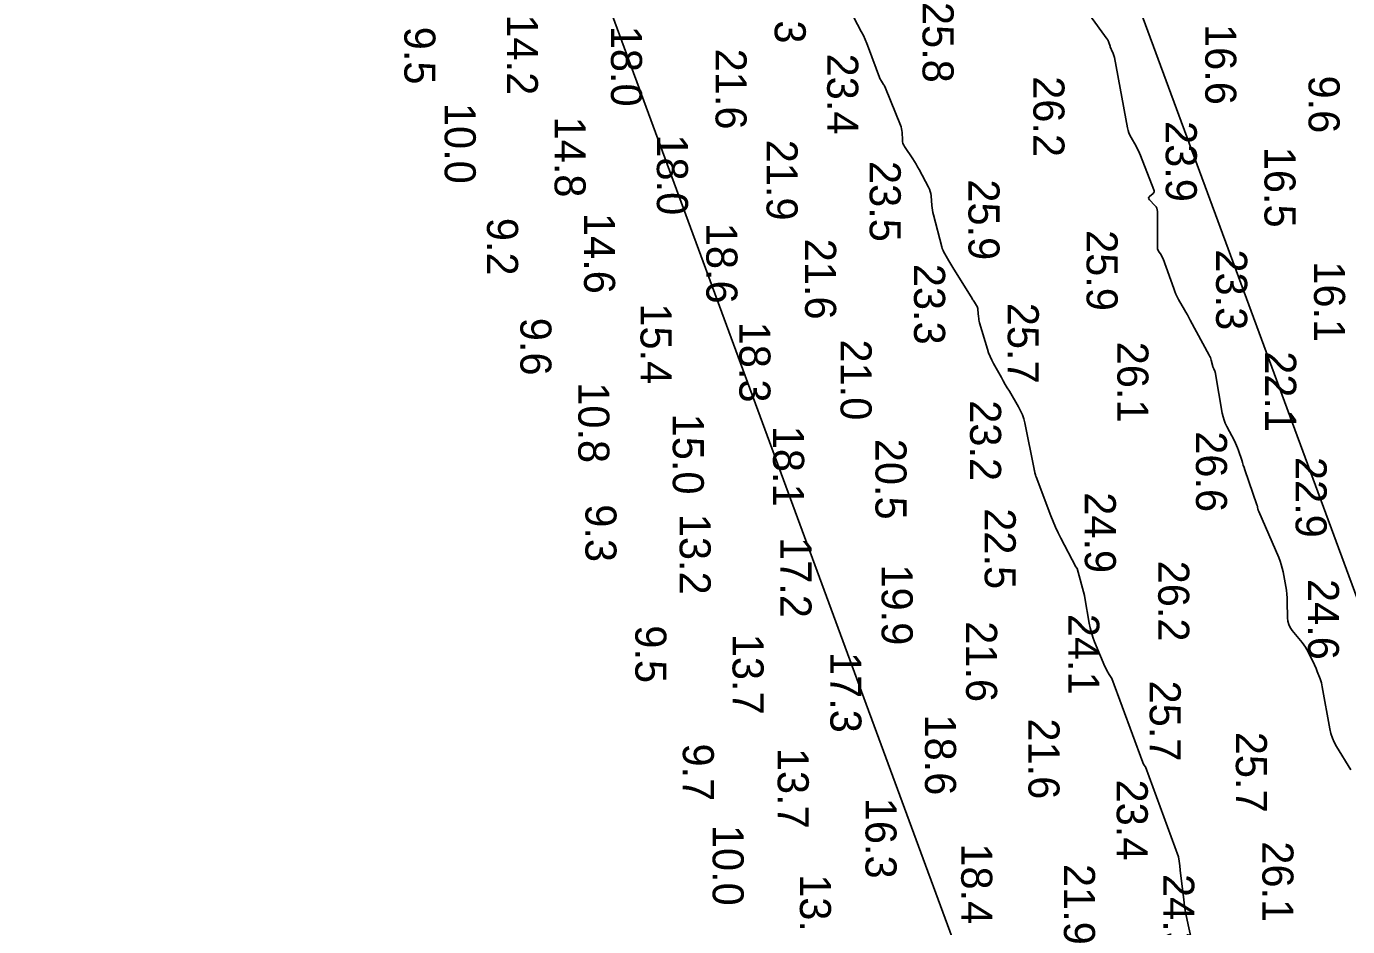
# Model space of a CAD drawing. Extents: x 1178573 to 1187098, y 693282 to 751751.
# Drawn here: x 1184917 to 1185449, y 735953 to 736315 of the extents above; entities that cross this region are included whole.
import ezdxf

# ---------------------------------------------------------------- set-up
doc = ezdxf.new("R2010")
doc.units = 0
for name, color, linetype in [('G-ANNO-PATT', 7, 'Continuous'), ('V-HYDS-MAJR', 7, 'Continuous'), ('V-HYDS-SOUN', 7, 'Continuous')]:
    doc.layers.add(name, color=color, linetype=linetype)

msp = doc.modelspace()

# ---------------------------------------------------------------- linework, layer by layer
at = {"layer": 'G-ANNO-PATT'}
for p, q in [((1184917.23, 736959.6), (1185542.3, 735264.1)), ((1185735.81, 735317.4), (1185139.49, 736934.9)), ((1185253.23, 736313.41), (1185248.66, 736322.17)), ((1185345.04, 736320.07), (1185352.17, 736310.33)), ((1185254.04, 736311.81), (1185253.23, 736313.41)), ((1185254.79, 736310.18), (1185254.04, 736311.81)), ((1185255.49, 736308.53), (1185254.79, 736310.18)), ((1185256.14, 736306.86), (1185255.49, 736308.53)), ((1185352.17, 736310.33), (1185352.39, 736310.01)), ((1185352.39, 736310.01), (1185352.57, 736309.67)), ((1185352.57, 736309.67), (1185352.73, 736309.32)), ((1185352.73, 736309.32), (1185352.86, 736308.95)), ((1185352.86, 736308.95), (1185353.32, 736307.45)), ((1185260.58, 736294.88), (1185256.14, 736306.86)), ((1185353.32, 736307.45), (1185353.44, 736307.08)), ((1185353.44, 736307.08), (1185353.58, 736306.72)), ((1185353.58, 736306.72), (1185353.73, 736306.35)), ((1185353.73, 736306.35), (1185353.89, 736306)), ((1185353.89, 736306), (1185354.61, 736304.49)), ((1185354.61, 736304.49), (1185354.78, 736304.12)), ((1185354.78, 736304.12), (1185354.91, 736303.74)), ((1185354.91, 736303.74), (1185355.03, 736303.35)), ((1185355.03, 736303.35), (1185355.11, 736302.95)), ((1185355.11, 736302.95), (1185360.38, 736274.62)), ((1185260.73, 736294.5), (1185260.58, 736294.88)), ((1185260.9, 736294.14), (1185260.73, 736294.5)), ((1185261.09, 736293.79), (1185260.9, 736294.14)), ((1185261.3, 736293.44), (1185261.09, 736293.79)), ((1185262.18, 736292.09), (1185261.3, 736293.44)), ((1185262.39, 736291.75), (1185262.18, 736292.09)), ((1185262.59, 736291.4), (1185262.39, 736291.75)), ((1185262.76, 736291.04), (1185262.59, 736291.4)), ((1185262.92, 736290.67), (1185262.76, 736291.04)), ((1185268.99, 736275.69), (1185262.92, 736290.67)), ((1185269.24, 736274.99), (1185268.99, 736275.69)), ((1185269.42, 736274.28), (1185269.24, 736274.99)), ((1185269.55, 736273.55), (1185269.42, 736274.28)), ((1185269.61, 736272.81), (1185269.55, 736273.55)), ((1185269.75, 736269.83), (1185269.61, 736272.81)), ((1185360.38, 736274.62), (1185360.61, 736273.63)), ((1185360.61, 736273.63), (1185360.91, 736272.66)), ((1185360.91, 736272.66), (1185361.3, 736271.71)), ((1185361.3, 736271.71), (1185361.77, 736270.8)), ((1185269.83, 736269.1), (1185269.75, 736269.83)), ((1185270, 736268.4), (1185269.83, 736269.1)), ((1185270.27, 736267.73), (1185270, 736268.4)), ((1185270.64, 736267.1), (1185270.27, 736267.73)), ((1185273.93, 736262.15), (1185270.64, 736267.1)), ((1185361.77, 736270.8), (1185363.8, 736267.21)), ((1185363.8, 736267.21), (1185364.29, 736266.31)), ((1185364.29, 736266.31), (1185364.75, 736265.38)), ((1185274.6, 736261.11), (1185273.93, 736262.15)), ((1185275.24, 736260.06), (1185274.6, 736261.11)), ((1185364.75, 736265.38), (1185365.17, 736264.45)), ((1185365.17, 736264.45), (1185365.57, 736263.5)), ((1185365.57, 736263.5), (1185371.01, 736249.72)), ((1185275.86, 736258.99), (1185275.24, 736260.06)), ((1185276.46, 736257.9), (1185275.86, 736258.99)), ((1185280.23, 736250.8), (1185276.46, 736257.9)), ((1185280.63, 736249.95), (1185280.23, 736250.8)), ((1185280.94, 736249.07), (1185280.63, 736249.95)), ((1185371.01, 736249.72), (1185371.12, 736249.3)), ((1185281.16, 736248.16), (1185280.94, 736249.07)), ((1185281.29, 736247.22), (1185281.16, 736248.16)), ((1185281.61, 736243.43), (1185281.29, 736247.22)), ((1185368.95, 736246.71), (1185368.85, 736246.39)), ((1185368.85, 736246.39), (1185368.92, 736246.06)), ((1185368.92, 736246.06), (1185369.16, 736245.73)), ((1185369.22, 736247.02), (1185368.95, 736246.71)), ((1185369.16, 736245.73), (1185371.4, 736243.38)), ((1185370.65, 736248.24), (1185369.22, 736247.02)), ((1185370.94, 736248.56), (1185370.65, 736248.24)), ((1185371.1, 736248.92), (1185370.94, 736248.56)), ((1185371.12, 736249.3), (1185371.1, 736248.92)), ((1185281.72, 736242.48), (1185281.61, 736243.43)), ((1185281.86, 736241.55), (1185281.72, 736242.48)), ((1185282.04, 736240.61), (1185281.86, 736241.55)), ((1185282.26, 736239.69), (1185282.04, 736240.61)), ((1185285.61, 736226.81), (1185282.26, 736239.69)), ((1185371.4, 736243.38), (1185371.83, 736242.85)), ((1185371.83, 736242.85), (1185372.13, 736242.27)), ((1185372.13, 736242.27), (1185372.31, 736241.65)), ((1185372.31, 736241.65), (1185372.37, 736240.98)), ((1185372.37, 736240.98), (1185372.36, 736226.65)), ((1185285.83, 736226.05), (1185285.61, 736226.81)), ((1185286.11, 736225.32), (1185285.83, 736226.05)), ((1185286.44, 736224.61), (1185286.11, 736225.32)), ((1185286.82, 736223.91), (1185286.44, 736224.61)), ((1185288.46, 736221.19), (1185286.82, 736223.91)), ((1185372.36, 736226.65), (1185372.39, 736226.22)), ((1185372.39, 736226.22), (1185372.48, 736225.8)), ((1185372.48, 736225.8), (1185372.64, 736225.41)), ((1185372.64, 736225.41), (1185372.86, 736225.03)), ((1185372.86, 736225.03), (1185373.86, 736223.56)), ((1185373.86, 736223.56), (1185374.1, 736223.19)), ((1185374.1, 736223.19), (1185374.31, 736222.8)), ((1185288.87, 736220.51), (1185288.46, 736221.19)), ((1185289.28, 736219.83), (1185288.87, 736220.51)), ((1185289.69, 736219.15), (1185289.28, 736219.83)), ((1185290.11, 736218.48), (1185289.69, 736219.15)), ((1185297.81, 736205.99), (1185290.11, 736218.48)), ((1185374.31, 736222.8), (1185374.5, 736222.4)), ((1185374.5, 736222.4), (1185374.66, 736221.99)), ((1185374.66, 736221.99), (1185378.94, 736209.96)), ((1185378.94, 736209.96), (1185379.37, 736208.84)), ((1185379.37, 736208.84), (1185379.84, 736207.75)), ((1185379.84, 736207.75), (1185380.36, 736206.68)), ((1185298.03, 736205.62), (1185297.81, 736205.99)), ((1185298.26, 736205.26), (1185298.03, 736205.62)), ((1185298.48, 736204.9), (1185298.26, 736205.26)), ((1185298.71, 736204.54), (1185298.48, 736204.9)), ((1185299.61, 736203.1), (1185298.71, 736204.54)), ((1185299.81, 736202.73), (1185299.61, 736203.1)), ((1185299.97, 736202.35), (1185299.81, 736202.73)), ((1185300.08, 736201.95), (1185299.97, 736202.35)), ((1185300.14, 736201.53), (1185300.08, 736201.95)), ((1185380.36, 736206.68), (1185380.92, 736205.63)), ((1185380.92, 736205.63), (1185383.29, 736201.48)), ((1185300.39, 736198.66), (1185300.14, 736201.53)), ((1185300.46, 736198.05), (1185300.39, 736198.66)), ((1185300.55, 736197.44), (1185300.46, 736198.05)), ((1185300.68, 736196.83), (1185300.55, 736197.44)), ((1185300.84, 736196.24), (1185300.68, 736196.83)), ((1185383.29, 736201.48), (1185383.87, 736200.45)), ((1185383.87, 736200.45), (1185384.45, 736199.4)), ((1185384.45, 736199.4), (1185385.03, 736198.36)), ((1185385.03, 736198.36), (1185385.6, 736197.31)), ((1185385.6, 736197.31), (1185393.28, 736183.16)), ((1185303.96, 736185.63), (1185300.84, 736196.24)), ((1185304.46, 736184.11), (1185303.96, 736185.63)), ((1185305.03, 736182.62), (1185304.46, 736184.11)), ((1185305.69, 736181.18), (1185305.03, 736182.62)), ((1185306.44, 736179.76), (1185305.69, 736181.18)), ((1185393.28, 736183.16), (1185393.51, 736182.69)), ((1185393.51, 736182.69), (1185393.72, 736182.21)), ((1185393.72, 736182.21), (1185393.89, 736181.72)), ((1185393.89, 736181.72), (1185394.04, 736181.21)), ((1185394.04, 736181.21), (1185394.68, 736178.68)), ((1185309.59, 736174.18), (1185306.44, 736179.76)), ((1185394.68, 736178.68), (1185394.76, 736178.42)), ((1185394.76, 736178.42), (1185394.84, 736178.17)), ((1185394.84, 736178.17), (1185394.93, 736177.92)), ((1185394.93, 736177.92), (1185395.03, 736177.67)), ((1185395.03, 736177.67), (1185395.47, 736176.68)), ((1185395.47, 736176.68), (1185395.57, 736176.43)), ((1185395.57, 736176.43), (1185395.65, 736176.18)), ((1185395.65, 736176.18), (1185395.72, 736175.92)), ((1185395.72, 736175.92), (1185395.78, 736175.66)), ((1185395.78, 736175.66), (1185398.51, 736159.83)), ((1185310.38, 736172.79), (1185309.59, 736174.18)), ((1185311.18, 736171.4), (1185310.38, 736172.79)), ((1185311.98, 736170.01), (1185311.18, 736171.4)), ((1185312.8, 736168.63), (1185311.98, 736170.01)), ((1185316.52, 736162.34), (1185312.8, 736168.63)), ((1185317.35, 736160.8), (1185316.52, 736162.34)), ((1185318.04, 736159.22), (1185317.35, 736160.8)), ((1185398.51, 736159.83), (1185398.81, 736158.43)), ((1185318.59, 736157.58), (1185318.04, 736159.22)), ((1185319, 736155.89), (1185318.59, 736157.58)), ((1185322.75, 736137.36), (1185319, 736155.89)), ((1185398.81, 736158.43), (1185399.21, 736157.07)), ((1185399.21, 736157.07), (1185399.72, 736155.75)), ((1185399.72, 736155.75), (1185400.34, 736154.46)), ((1185400.34, 736154.46), (1185403.38, 736148.68)), ((1185403.38, 736148.68), (1185403.85, 736147.75)), ((1185403.85, 736147.75), (1185404.27, 736146.81)), ((1185404.27, 736146.81), (1185404.66, 736145.85)), ((1185404.66, 736145.85), (1185405, 736144.88)), ((1185405, 736144.88), (1185406.3, 736140.94)), ((1185406.3, 736140.94), (1185406.63, 736139.96)), ((1185406.63, 736139.96), (1185406.96, 736138.98)), ((1185406.96, 736138.98), (1185407.29, 736137.99)), ((1185322.78, 736137.23), (1185322.75, 736137.36)), ((1185322.81, 736137.1), (1185322.78, 736137.23)), ((1185322.83, 736136.97), (1185322.81, 736137.1)), ((1185322.86, 736136.84), (1185322.83, 736136.97)), ((1185322.97, 736136.32), (1185322.86, 736136.84)), ((1185323, 736136.19), (1185322.97, 736136.32)), ((1185323.03, 736136.07), (1185323, 736136.19)), ((1185323.06, 736135.94), (1185323.03, 736136.07)), ((1185323.09, 736135.81), (1185323.06, 736135.94)), ((1185323.32, 736134.99), (1185323.09, 736135.81)), ((1185323.37, 736134.82), (1185323.32, 736134.99)), ((1185323.42, 736134.64), (1185323.37, 736134.82)), ((1185323.48, 736134.46), (1185323.42, 736134.64)), ((1185323.55, 736134.29), (1185323.48, 736134.46)), ((1185329.51, 736118.5), (1185323.55, 736134.29)), ((1185407.29, 736137.99), (1185407.63, 736137.01)), ((1185407.63, 736137.01), (1185412.46, 736122.96)), ((1185412.46, 736122.96), (1185412.52, 736122.76)), ((1185412.52, 736122.76), (1185412.58, 736122.56)), ((1185412.58, 736122.56), (1185412.63, 736122.36)), ((1185412.63, 736122.36), (1185412.67, 736122.16)), ((1185412.67, 736122.16), (1185412.87, 736121.11)), ((1185330.42, 736116.22), (1185329.51, 736118.5)), ((1185412.87, 736121.11), (1185412.89, 736121.03)), ((1185412.89, 736121.03), (1185412.91, 736120.96)), ((1185412.91, 736120.96), (1185412.94, 736120.88)), ((1185412.94, 736120.88), (1185412.98, 736120.81)), ((1185412.98, 736120.81), (1185413.12, 736120.52)), ((1185413.12, 736120.52), (1185413.15, 736120.45)), ((1185413.15, 736120.45), (1185413.19, 736120.37)), ((1185413.19, 736120.37), (1185413.22, 736120.3)), ((1185413.22, 736120.3), (1185413.25, 736120.23)), ((1185413.25, 736120.23), (1185421.22, 736101.75)), ((1185331.39, 736113.97), (1185330.42, 736116.22)), ((1185332.42, 736111.75), (1185331.39, 736113.97)), ((1185333.53, 736109.56), (1185332.42, 736111.75)), ((1185339.6, 736097.97), (1185333.53, 736109.56)), ((1185421.22, 736101.75), (1185421.77, 736100.35)), ((1185340.03, 736097.3), (1185339.6, 736097.97)), ((1185343.09, 736086.53), (1185340.03, 736097.3)), ((1185421.77, 736100.35), (1185422.25, 736098.92)), ((1185422.25, 736098.92), (1185422.64, 736097.48)), ((1185422.64, 736097.48), (1185422.96, 736096)), ((1185422.96, 736096), (1185424.05, 736090.06)), ((1185343.18, 736085.6), (1185343.09, 736086.53)), ((1185344.95, 736075.35), (1185343.18, 736085.6)), ((1185424.05, 736090.06), (1185424.29, 736088.58)), ((1185424.29, 736088.58), (1185424.47, 736087.08)), ((1185424.47, 736087.08), (1185424.59, 736085.58)), ((1185424.59, 736085.58), (1185424.64, 736084.07)), ((1185424.64, 736084.07), (1185424.73, 736077.51)), ((1185345.34, 736073.44), (1185344.95, 736075.35)), ((1185424.73, 736077.51), (1185424.86, 736076.12)), ((1185424.86, 736076.12), (1185425.22, 736074.81)), ((1185425.22, 736074.81), (1185425.79, 736073.57)), ((1185345.83, 736071.56), (1185345.34, 736073.44)), ((1185346.42, 736069.71), (1185345.83, 736071.56)), ((1185347.12, 736067.9), (1185346.42, 736069.71)), ((1185425.79, 736073.57), (1185426.59, 736072.42)), ((1185426.59, 736072.42), (1185430.58, 736067.55)), ((1185351.26, 736057.94), (1185347.12, 736067.9)), ((1185430.58, 736067.55), (1185431.29, 736066.64)), ((1185431.29, 736066.64), (1185431.94, 736065.69)), ((1185431.94, 736065.69), (1185432.53, 736064.71)), ((1185432.53, 736064.71), (1185433.07, 736063.69)), ((1185433.07, 736063.69), (1185435.44, 736058.93)), ((1185435.44, 736058.93), (1185435.79, 736058.2)), ((1185351.45, 736057.51), (1185351.26, 736057.94)), ((1185351.65, 736057.09), (1185351.45, 736057.51)), ((1185351.86, 736056.68), (1185351.65, 736057.09)), ((1185352.08, 736056.28), (1185351.86, 736056.68)), ((1185353.01, 736054.66), (1185352.08, 736056.28)), ((1185353.24, 736054.26), (1185353.01, 736054.66)), ((1185353.49, 736053.87), (1185353.24, 736054.26)), ((1185353.75, 736053.49), (1185353.49, 736053.87)), ((1185354.03, 736053.12), (1185353.75, 736053.49)), ((1185366.47, 736019.31), (1185354.03, 736053.12)), ((1185435.79, 736058.2), (1185436.12, 736057.46)), ((1185436.12, 736057.46), (1185436.44, 736056.71)), ((1185436.44, 736056.71), (1185436.73, 736055.95)), ((1185436.73, 736055.95), (1185437.88, 736052.9)), ((1185437.88, 736052.9), (1185438.15, 736052.13)), ((1185438.15, 736052.13), (1185438.38, 736051.35)), ((1185438.38, 736051.35), (1185438.58, 736050.56)), ((1185438.58, 736050.56), (1185438.74, 736049.77)), ((1185438.74, 736049.77), (1185441.79, 736032.8)), ((1185441.79, 736032.8), (1185442.21, 736030.94)), ((1185442.21, 736030.94), (1185442.8, 736029.14)), ((1185442.8, 736029.14), (1185443.55, 736027.4)), ((1185443.55, 736027.4), (1185444.46, 736025.72)), ((1185444.46, 736025.72), (1185450.17, 736016.3)), ((1185366.96, 736018.4), (1185366.47, 736019.31)), ((1185367.6, 736017.55), (1185366.96, 736018.4)), ((1185380.86, 735981.31), (1185367.6, 736017.55)), ((1185381.14, 735979.52), (1185380.86, 735981.31)), ((1185381.39, 735977.73), (1185381.14, 735979.52)), ((1185381.61, 735975.94), (1185381.39, 735977.73)), ((1185382.98, 735964.03), (1185381.61, 735975.94)), ((1185383.3, 735961.49), (1185382.98, 735964.03)), ((1185383.7, 735958.97), (1185383.3, 735961.49)), ((1185384.17, 735956.47), (1185383.7, 735958.97)), ((1185384.7, 735953.97), (1185384.17, 735956.47)), ((1185387.77, 735940.63), (1185384.7, 735953.97))]:
    msp.add_line(p, q, dxfattribs=at)
at = {"layer": 'V-HYDS-MAJR'}
for points in [[(1185387.77, 735940.63), (1185384.7, 735953.97), (1185384.17, 735956.47), (1185383.7, 735958.97), (1185383.3, 735961.49), (1185382.98, 735964.03), (1185381.61, 735975.94), (1185381.39, 735977.73), (1185381.14, 735979.52), (1185380.86, 735981.31), (1185367.6, 736017.55), (1185366.96, 736018.4), (1185366.47, 736019.31), (1185354.03, 736053.12), (1185353.75, 736053.49), (1185353.49, 736053.87), (1185353.24, 736054.26), (1185353.01, 736054.66), (1185352.08, 736056.28), (1185351.86, 736056.68), (1185351.65, 736057.09), (1185351.45, 736057.51), (1185351.26, 736057.94), (1185347.12, 736067.9), (1185346.42, 736069.71), (1185345.83, 736071.56), (1185345.34, 736073.44), (1185344.95, 736075.35), (1185343.18, 736085.6), (1185343.09, 736086.53), (1185340.03, 736097.3), (1185339.6, 736097.97), (1185333.53, 736109.56), (1185332.42, 736111.75), (1185331.39, 736113.97), (1185330.42, 736116.22), (1185329.51, 736118.5), (1185323.55, 736134.29), (1185323.48, 736134.46), (1185323.42, 736134.64), (1185323.37, 736134.82), (1185323.32, 736134.99), (1185323.09, 736135.81), (1185323.06, 736135.94), (1185323.03, 736136.07), (1185323, 736136.19), (1185322.97, 736136.32), (1185322.86, 736136.84), (1185322.83, 736136.97), (1185322.81, 736137.1), (1185322.78, 736137.23), (1185322.75, 736137.36), (1185319, 736155.89), (1185318.59, 736157.58), (1185318.04, 736159.22), (1185317.35, 736160.8), (1185316.52, 736162.34), (1185312.8, 736168.63), (1185311.98, 736170.01), (1185311.18, 736171.4), (1185310.38, 736172.79), (1185309.59, 736174.18), (1185306.44, 736179.76), (1185305.69, 736181.18), (1185305.03, 736182.62), (1185304.46, 736184.11), (1185303.96, 736185.63), (1185300.84, 736196.24), (1185300.68, 736196.83), (1185300.55, 736197.44), (1185300.46, 736198.05), (1185300.39, 736198.66), (1185300.14, 736201.53), (1185300.08, 736201.95), (1185299.97, 736202.35), (1185299.81, 736202.73), (1185299.61, 736203.1), (1185298.71, 736204.54), (1185298.48, 736204.9), (1185298.26, 736205.26), (1185298.03, 736205.62), (1185297.81, 736205.99), (1185290.11, 736218.48), (1185289.69, 736219.15), (1185289.28, 736219.83), (1185288.87, 736220.51), (1185288.46, 736221.19), (1185286.82, 736223.91), (1185286.44, 736224.61), (1185286.11, 736225.32), (1185285.83, 736226.05), (1185285.61, 736226.81), (1185282.26, 736239.69), (1185282.04, 736240.61), (1185281.86, 736241.55), (1185281.72, 736242.48), (1185281.61, 736243.43), (1185281.29, 736247.22), (1185281.16, 736248.16), (1185280.94, 736249.07), (1185280.63, 736249.95), (1185280.23, 736250.8), (1185276.46, 736257.9), (1185275.86, 736258.99), (1185275.24, 736260.06), (1185274.6, 736261.11), (1185273.93, 736262.15), (1185270.64, 736267.1), (1185270.27, 736267.73), (1185270, 736268.4), (1185269.83, 736269.1), (1185269.75, 736269.83), (1185269.61, 736272.81), (1185269.55, 736273.55), (1185269.42, 736274.28), (1185269.24, 736274.99), (1185268.99, 736275.69), (1185262.92, 736290.67), (1185262.76, 736291.04), (1185262.59, 736291.4), (1185262.39, 736291.75), (1185262.18, 736292.09), (1185261.3, 736293.44), (1185261.09, 736293.79), (1185260.9, 736294.14), (1185260.73, 736294.5), (1185260.58, 736294.88), (1185256.14, 736306.86), (1185255.49, 736308.53), (1185254.79, 736310.18), (1185254.04, 736311.81), (1185253.23, 736313.41), (1185248.66, 736322.17)], [(1185345.04, 736320.07), (1185352.17, 736310.33), (1185352.39, 736310.01), (1185352.57, 736309.67), (1185352.73, 736309.32), (1185352.86, 736308.95), (1185353.32, 736307.45), (1185353.44, 736307.08), (1185353.58, 736306.72), (1185353.73, 736306.35), (1185353.89, 736306), (1185354.61, 736304.49), (1185354.78, 736304.12), (1185354.91, 736303.74), (1185355.03, 736303.35), (1185355.11, 736302.95), (1185360.38, 736274.62), (1185360.61, 736273.63), (1185360.91, 736272.66), (1185361.3, 736271.71), (1185361.77, 736270.8), (1185363.8, 736267.21), (1185364.29, 736266.31), (1185364.75, 736265.38), (1185365.17, 736264.45), (1185365.57, 736263.5), (1185371.01, 736249.72), (1185371.12, 736249.3), (1185371.1, 736248.92), (1185370.94, 736248.56), (1185370.65, 736248.24), (1185369.22, 736247.02), (1185368.95, 736246.71), (1185368.85, 736246.39), (1185368.92, 736246.06), (1185369.16, 736245.73), (1185371.4, 736243.38), (1185371.83, 736242.85), (1185372.13, 736242.27), (1185372.31, 736241.65), (1185372.37, 736240.98), (1185372.36, 736226.65), (1185372.39, 736226.22), (1185372.48, 736225.8), (1185372.64, 736225.41), (1185372.86, 736225.03), (1185373.86, 736223.56), (1185374.1, 736223.19), (1185374.31, 736222.8), (1185374.5, 736222.4), (1185374.66, 736221.99), (1185378.94, 736209.96), (1185379.37, 736208.84), (1185379.84, 736207.75), (1185380.36, 736206.68), (1185380.92, 736205.63), (1185383.29, 736201.48), (1185383.87, 736200.45), (1185384.45, 736199.4), (1185385.03, 736198.36), (1185385.6, 736197.31), (1185393.28, 736183.16), (1185393.51, 736182.69), (1185393.72, 736182.21), (1185393.89, 736181.72), (1185394.04, 736181.21), (1185394.68, 736178.68), (1185394.76, 736178.42), (1185394.84, 736178.17), (1185394.93, 736177.92), (1185395.03, 736177.67), (1185395.47, 736176.68), (1185395.57, 736176.43), (1185395.65, 736176.18), (1185395.72, 736175.92), (1185395.78, 736175.66), (1185398.51, 736159.83), (1185398.81, 736158.43), (1185399.21, 736157.07), (1185399.72, 736155.75), (1185400.34, 736154.46), (1185403.38, 736148.68), (1185403.85, 736147.75), (1185404.27, 736146.81), (1185404.66, 736145.85), (1185405, 736144.88), (1185406.3, 736140.94), (1185406.63, 736139.96), (1185406.96, 736138.98), (1185407.29, 736137.99), (1185407.63, 736137.01), (1185412.46, 736122.96), (1185412.52, 736122.76), (1185412.58, 736122.56), (1185412.63, 736122.36), (1185412.67, 736122.16), (1185412.87, 736121.11), (1185412.89, 736121.03), (1185412.91, 736120.96), (1185412.94, 736120.88), (1185412.98, 736120.81), (1185413.12, 736120.52), (1185413.15, 736120.45), (1185413.19, 736120.37), (1185413.22, 736120.3), (1185413.25, 736120.23), (1185421.22, 736101.75), (1185421.77, 736100.35), (1185422.25, 736098.92), (1185422.64, 736097.48), (1185422.96, 736096), (1185424.05, 736090.06), (1185424.29, 736088.58), (1185424.47, 736087.08), (1185424.59, 736085.58), (1185424.64, 736084.07), (1185424.73, 736077.51), (1185424.86, 736076.12), (1185425.22, 736074.81), (1185425.79, 736073.57), (1185426.59, 736072.42), (1185430.58, 736067.55), (1185431.29, 736066.64), (1185431.94, 736065.69), (1185432.53, 736064.71), (1185433.07, 736063.69), (1185435.44, 736058.93), (1185435.79, 736058.2), (1185436.12, 736057.46), (1185436.44, 736056.71), (1185436.73, 736055.95), (1185437.88, 736052.9), (1185438.15, 736052.13), (1185438.38, 736051.35), (1185438.58, 736050.56), (1185438.74, 736049.77), (1185441.79, 736032.8), (1185442.21, 736030.94), (1185442.8, 736029.14), (1185443.55, 736027.4), (1185444.46, 736025.72), (1185450.17, 736016.3)]]:
    msp.add_lwpolyline(points, dxfattribs=at)

# ---------------------------------------------------------------- texts
at = {"layer": 'V-HYDS-SOUN'}
for s, p in [('23.3 ', (1185218.36, 736341.12)), ('25.8 ', (1185277.88, 736325.31)), ('14.2 ', (1185110.57, 736320.29)), ('9.5', (1185069.32, 736315.33)), ('18.0 ', (1185152.48, 736315.71)), ('16.6 ', (1185391.65, 736316.42)), ('21.6 ', (1185194.57, 736306.51)), ('23.4 ', (1185239.49, 736304.52)), ('26.2 ', (1185322.48, 736295.42)), ('9.6', (1185433.23, 736295.69)), ('10.0 ', (1185085.55, 736284.67)), ('14.8 ', (1185129.79, 736279.18)), ('23.9 ', (1185375.75, 736277.38)), ('18.0 ', (1185170.95, 736272.01)), ('21.9 ', (1185215.09, 736269.86)), ('16.5 ', (1185415.48, 736267.02)), ('23.5 ', (1185256.59, 736261.31)), ('25.9 ', (1185296.35, 736253.92)), ('14.6 ', (1185141.65, 736240.4)), ('9.2', (1185102.59, 736238.44)), ('18.6 ', (1185190.87, 736236.43)), ('21.6 ', (1185230.6, 736230.03)), ('25.9 ', (1185343.89, 736233.51)), ('23.3 ', (1185396.02, 736225.74)), ('23.3 ', (1185274.46, 736219.93)), ('16.1 ', (1185435.43, 736220.94)), ('15.4 ', (1185164.36, 736204.03)), ('25.7 ', (1185312.16, 736204.25)), ('9.6', (1185116.01, 736198.22)), ('18.3 ', (1185204.15, 736196.64)), ('21.0 ', (1185244.87, 736189.49)), ('26.1 ', (1185356.27, 736188.59)), ('22.1 ', (1185415.75, 736184.78)), ('10.8 ', (1185139.33, 736172.29)), ('23.2 ', (1185296.99, 736165.04)), ('15.0 ', (1185177.35, 736159.64)), ('18.1 ', (1185217.72, 736154.76)), ('20.5 ', (1185258.92, 736149.54)), ('26.6 ', (1185387.91, 736152.57)), ('22.9 ', (1185428.01, 736142.24)), ('9.3', (1185142.19, 736123.18)), ('24.9 ', (1185343.17, 736128.03)), ('13.2 ', (1185180.1, 736119.34)), ('22.5 ', (1185302.88, 736121.58)), ('17.2 ', (1185220.68, 736109.99)), ('19.9 ', (1185261.41, 736098.97)), ('26.2 ', (1185372.71, 736100.5)), ('24.6 ', (1185432.96, 736093.13)), ('21.6 ', (1185295.39, 736076.13)), ('24.1 ', (1185336.51, 736079.11)), ('9.5', (1185162.27, 736074.48)), ('13.7 ', (1185201.4, 736071.08)), ('17.3 ', (1185240.77, 736063.76)), ('25.7 ', (1185369.28, 736052.25)), ('18.6 ', (1185278.86, 736038.6)), ('21.6 ', (1185320.49, 736037.02)), ('25.7 ', (1185403.96, 736031.64)), ('9.7', (1185181.39, 736026.93)), ('13.7 ', (1185219.57, 736025.18)), ('23.4 ', (1185356.02, 736012.43)), ('16.3 ', (1185254.91, 736005.1)), ('10.0 ', (1185193.39, 735994.19)), ('18.4 ', (1185293.43, 735986.74)), ('26.1 ', (1185414.63, 735987.57)), ('21.9 ', (1185334.77, 735978.46)), ('24.3 ', (1185374.72, 735974.42)), ('13.1 ', (1185228.51, 735974.35))]:
    msp.add_text(s, height=12.5, rotation=270, dxfattribs=at).set_placement(p)

doc.saveas('drawing.dxf')
